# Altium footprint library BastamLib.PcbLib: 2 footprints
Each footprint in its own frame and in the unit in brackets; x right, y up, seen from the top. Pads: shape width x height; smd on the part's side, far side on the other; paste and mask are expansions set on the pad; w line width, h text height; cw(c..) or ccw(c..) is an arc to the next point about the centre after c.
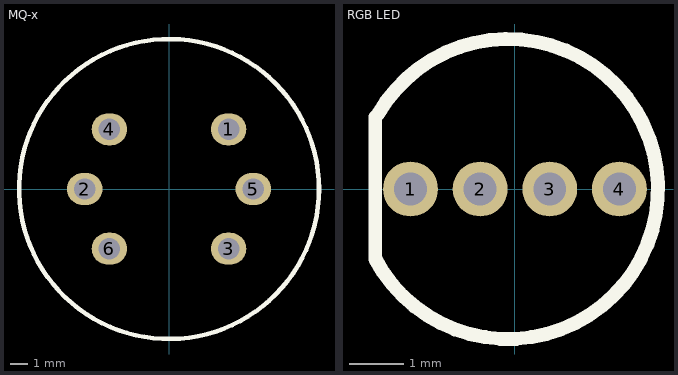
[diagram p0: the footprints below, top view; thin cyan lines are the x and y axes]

## MQ-x [mm]
pads (6):
  oval 2x1.8 hole 1.2: 1(3.359,3.359) 2(-4.75,0) 3(3.359,-3.359) 4(-3.359,3.359) 5(4.75,0) 6(-3.359,-3.359)
Top Overlay:
  circle w0.254: c0,0 r8.45

## RGB LED [mm]
pads (4):
  round 1 hole 0.6: 1(-1.905,0) 2(-0.635,0) 3(0.635,0) 4(1.905,0)
Top Overlay:
  lines w0.254: -2.548,1.312 -2.548,-1.274 ccw(c-0.127,0) -2.502,1.357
